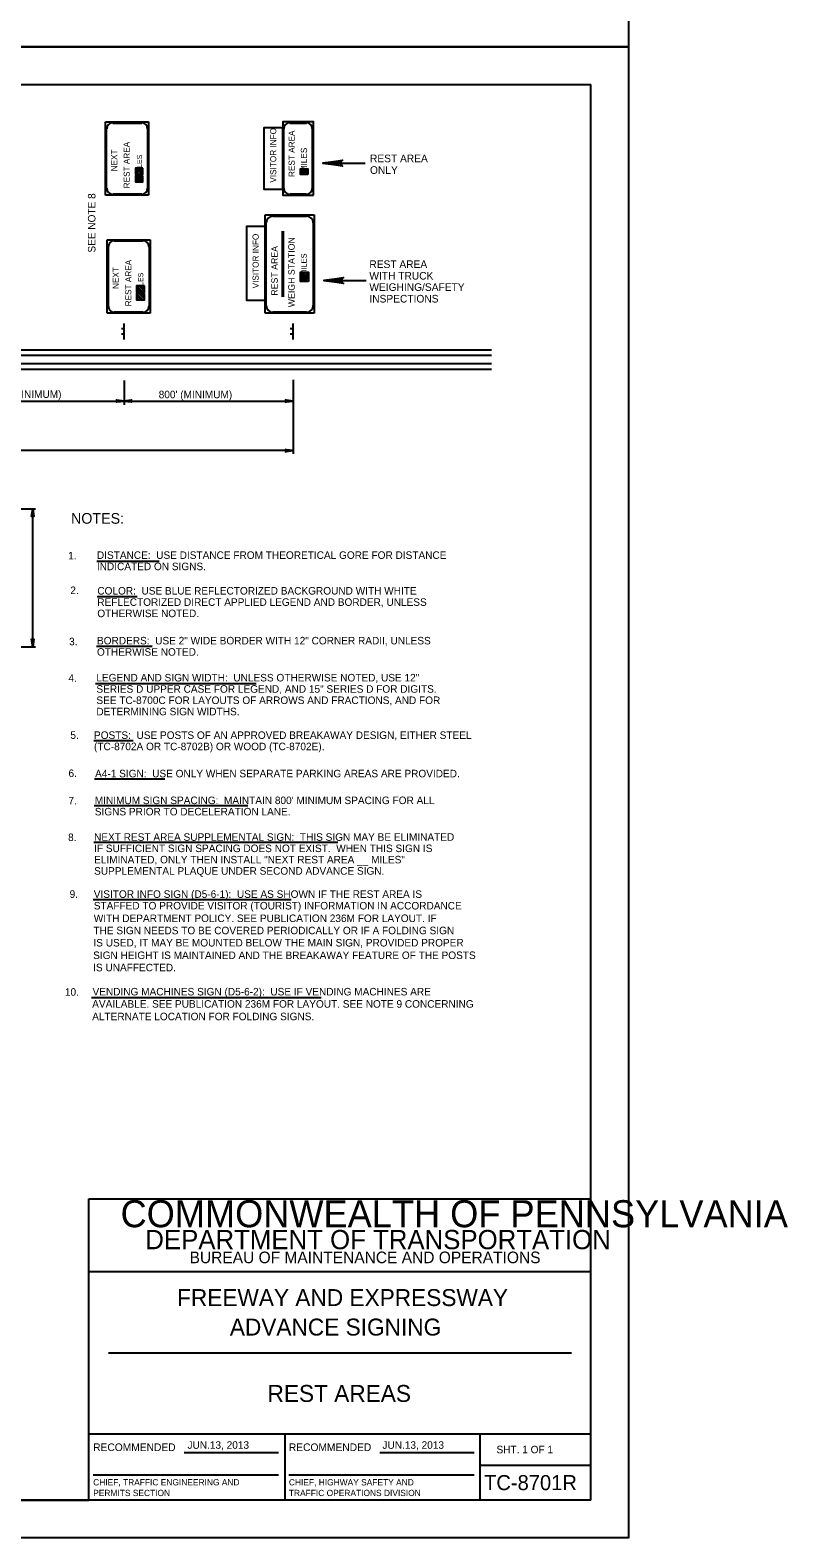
# Model space of a CAD drawing. Extents: x 649604 to 650509, y 298458 to 299646.
# Drawn here: x 650207 to 650509, y 298458 to 299058 of the extents above; entities that cross this region are included whole.
import ezdxf

# ---------------------------------------------------------------- set-up
doc = ezdxf.new("R2010")
doc.units = 0
for name, color, linetype in [('1', 7, 'Continuous'), ('2', 7, 'Continuous'), ('3', 7, 'Continuous'), ('PLT-BNDY', 7, 'Continuous')]:
    doc.layers.add(name, color=color, linetype=linetype)

# ---------------------------------------------------------------- blocks, each defined once
blk = doc.blocks.new('RARROW')
at = {"layer": '3'}
blk.add_lwpolyline([(-2.2695, 0.285), (-2.184875, 0.12075), (0, 0), (-2.2695, 0.285), (-2.38575, 0.384625), (0, 0), (-2.183125, -0.108), (-2.262875, -0.2705), (0, 0), (-2.38575, -0.379125), (-2.262875, -0.2705)], dxfattribs=at)

msp = doc.modelspace()

# ---------------------------------------------------------------- linework, layer by layer
at = {"layer": '1'}
for p, q in [((649644.31, 299036.63), (650430.31, 299036.63)), ((650430.31, 298472.63), (650430.31, 299036.63)), ((650230.31, 298472.63), (650230.31, 298592.63)), ((650230.31, 298592.63), (650430.31, 298592.63)), ((650430.31, 298563.63), (650230.31, 298563.63)), ((650238.06, 298531.31), (650422.56, 298531.31)), ((650230.31, 298499), (650430.31, 298499)), ((650308.31, 298499), (650308.31, 298472.63)), ((650386.19, 298472.63), (650386.19, 298499)), ((650268.24, 298491.57), (650305.87, 298491.57)), ((650346.24, 298491.57), (650383.87, 298491.57)), ((650386.19, 298486.63), (650430.31, 298486.63)), ((650231.99, 298482.68), (650305.87, 298482.68)), ((650309.99, 298482.68), (650383.87, 298482.68)), ((650430.31, 298472.63), (649644.31, 298472.63)), ((649644.31, 298472.63), (650230.31, 298472.63))]:
    msp.add_line(p, q, dxfattribs=at)
at = {"layer": '2'}
for p, q in [((650236.94, 298992.5), (650236.94, 299021.75)), ((650236.94, 299021.75), (650254.06, 299021.75)), ((650237.31, 298995.25), (650237.31, 299018.88)), ((650239.81, 299021.25), (650251.31, 299021.25)), ((650253.69, 299018.88), (650253.69, 298995.25)), ((650254.06, 299021.75), (650254.06, 298992.5)), ((650310.31, 299021.25), (650316.94, 299021.25)), ((650323.56, 299005.25), (650340.44, 299005.25)), ((650254.06, 298992.5), (650236.94, 298992.5)), ((650251.31, 298992.88), (650239.81, 298992.88)), ((650300.56, 298945.5), (650300.56, 298984.63)), ((650303.56, 298984.13), (650317.06, 298984.13)), ((650320.06, 298984.63), (650320.06, 298945.5)), ((650300.94, 298948.5), (650300.94, 298981.63)), ((650307.44, 298952), (650307.44, 298978.13)), ((650307.56, 298952), (650307.56, 298978.13)), ((650307.69, 298952), (650307.69, 298978.13)), ((650307.81, 298952), (650307.81, 298978.13)), ((650307.81, 298952), (650307.81, 298978.13)), ((650319.69, 298981.63), (650319.69, 298948.5)), ((650237.56, 298945.5), (650237.56, 298974.75)), ((650237.56, 298974.75), (650254.69, 298974.75)), ((650238.06, 298948.25), (650238.06, 298971.88)), ((650240.31, 298974.38), (650251.81, 298974.38)), ((650254.31, 298971.88), (650254.31, 298948.25)), ((650254.69, 298974.75), (650254.69, 298945.5)), ((650323.94, 298958.5), (650340.81, 298958.5)), ((650254.69, 298945.5), (650237.56, 298945.5)), ((650251.81, 298945.88), (650240.31, 298945.88)), ((650244.31, 298935), (650244.31, 298941.38)), ((650311.69, 298935), (650311.69, 298941.38)), ((650244.31, 298939.25), (650243.31, 298939.25)), ((650244.31, 298937.13), (650243.31, 298937.13)), ((650311.69, 298939.25), (650310.56, 298939.25)), ((650311.69, 298937.13), (650310.56, 298937.13)), ((649664.19, 298928.75), (650390.69, 298928.75)), ((649946.56, 298930.88), (650390.69, 298930.88)), ((650330.44, 298930.88), (650330.44, 298930.88)), ((649664.19, 298925.5), (650390.69, 298925.5)), ((649664.19, 298923.25), (650390.69, 298923.25)), ((650244.31, 298918.63), (650244.31, 298909)), ((650311.69, 298919), (650311.69, 298889.5)), ((650176.94, 298910.5), (650244.31, 298910.5)), ((650244.31, 298910.5), (650311.69, 298910.5)), ((650311.69, 298890.75), (649881.31, 298890.75)), ((650181.27, 298867.5), (650209, 298867.5)), ((650207.88, 298812.63), (650207.88, 298867.5)), ((650233.42, 298846.75), (650258.31, 298846.75)), ((650233.57, 298832.66), (650249.5, 298832.66)), ((650181.27, 298812.63), (650209, 298812.63)), ((650233.32, 298812.8), (650255.5, 298812.8)), ((650232.96, 298797.93), (650297, 298797.93)), ((650232.22, 298775.29), (650247.93, 298775.29)), ((650232.57, 298759.98), (650260.48, 298759.98)), ((650232.31, 298749.4), (650293.65, 298749.4)), ((650232.3, 298734.76), (650329.5, 298734.76)), ((650231.91, 298711.95), (650310.87, 298711.95)), ((650231.31, 298672.83), (650322.82, 298672.83))]:
    msp.add_line(p, q, dxfattribs=at)
for points in [[(650307.56, 298994.88), (650307.56, 299019.38), (650299.94, 299019.38), (650299.94, 298994.88)], [(650319.81, 298992.5), (650319.81, 299021.75), (650307.56, 299021.75), (650307.56, 298992.5)], [(650251.81, 299003.25), (650248.81, 299003.25), (650248.81, 299000.88), (650251.81, 299000.88)], [(650251.81, 299000.25), (650248.81, 299000.25), (650248.81, 298997.88), (650251.81, 298997.88)], [(650317.56, 299000.75), (650314.56, 299000.75), (650314.56, 299003), (650317.56, 299003)], [(650300.56, 298950.63), (650300.56, 298980), (650293.06, 298980), (650293.06, 298950.63)], [(650317.81, 298958.13), (650314.56, 298958.13), (650314.56, 298961.88), (650317.81, 298961.88)], [(650252.44, 298956.38), (650249.31, 298956.38), (650249.31, 298953.88), (650252.44, 298953.88)], [(650252.44, 298953.38), (650249.31, 298953.38), (650249.31, 298950.88), (650252.44, 298950.88)]]:
    msp.add_lwpolyline(points, close=True, dxfattribs=at)
for points in [[(650307.94, 298995.25), (650307.94, 299018.88)], [(650319.31, 299018.88), (650319.31, 298995.25)], [(650331.06, 299004.38), (650330.69, 299005), (650323.56, 299005.25), (650331.06, 299004.38), (650331.31, 299004.13), (650323.56, 299005.25), (650330.69, 299005.75), (650330.94, 299006.25), (650323.56, 299005.25), (650331.31, 299006.5), (650330.94, 299006.25)], [(650251.31, 299000.88), (650248.81, 299003.25)], [(650250.31, 299000.88), (650248.81, 299002.5)], [(650249.44, 299000.88), (650248.81, 299001.75)], [(650251.31, 298997.88), (650248.81, 299000.25)], [(650251.81, 298998.13), (650249.56, 299000.25)], [(650251.81, 299001.13), (650249.69, 299003.25)], [(650251.81, 299002), (650250.44, 299003.25)], [(650251.81, 298998.88), (650250.44, 299000.25)], [(650251.81, 299003), (650251.44, 299003.25)], [(650251.81, 298999.88), (650251.44, 299000.25)], [(650316.81, 299000.75), (650314.56, 299003)], [(650316.31, 299000.75), (650314.56, 299002.5)], [(650315.81, 299000.75), (650314.56, 299002)], [(650315.44, 299000.75), (650314.56, 299001.63)], [(650314.94, 299000.75), (650314.56, 299001.13)], [(650317.19, 299000.75), (650314.81, 299003)], [(650317.56, 299000.88), (650315.19, 299003)], [(650317.56, 299001.38), (650315.69, 299003)], [(650317.56, 299001.88), (650316.19, 299003)], [(650317.56, 299002.25), (650316.69, 299003)], [(650317.56, 299002.75), (650317.06, 299003)], [(650250.31, 298997.88), (650248.81, 298999.5)], [(650249.44, 298997.88), (650248.81, 298998.5)], [(650316.94, 298992.88), (650310.31, 298992.88)], [(650300.56, 298984.63), (650302.94, 298984.63), (650305.56, 298984.63), (650307.69, 298984.63), (650309.69, 298984.63), (650312.31, 298984.63), (650314.56, 298984.63), (650315.06, 298984.63), (650317.06, 298984.63), (650317.81, 298984.63), (650320.06, 298984.63)], [(650317.81, 298958.75), (650314.56, 298961.88)], [(650317.31, 298958.13), (650314.56, 298961.13)], [(650316.44, 298958.13), (650314.56, 298960.13)], [(650315.56, 298958.13), (650314.56, 298959.25)], [(650314.56, 298958.13), (650314.56, 298958.25)], [(650317.81, 298959.63), (650315.44, 298961.88)], [(650317.81, 298960.5), (650316.44, 298961.88)], [(650317.81, 298961.5), (650317.31, 298961.88)], [(650331.31, 298957.63), (650331.19, 298958.13), (650323.94, 298958.5), (650331.31, 298957.63), (650331.69, 298957.38), (650323.94, 298958.5), (650331.19, 298959), (650331.31, 298959.5), (650323.94, 298958.5), (650331.69, 298959.75), (650331.31, 298959.5)], [(650251.81, 298953.88), (650249.31, 298956.38)], [(650251.06, 298953.88), (650249.31, 298955.5)], [(650250.19, 298953.88), (650249.31, 298954.75)], [(650251.81, 298950.88), (650249.31, 298953.38)], [(650251.06, 298950.88), (650249.31, 298952.5)], [(650252.44, 298954.25), (650250.31, 298956.38)], [(650252.44, 298951.25), (650250.31, 298953.38)], [(650252.44, 298955.13), (650251.19, 298956.38)], [(650252.44, 298952), (650251.19, 298953.38)], [(650252.44, 298955.88), (650252.06, 298956.38)], [(650252.44, 298952.88), (650252.06, 298953.38)], [(650250.19, 298950.88), (650249.31, 298951.5)], [(650320.06, 298945.5), (650300.56, 298945.5)], [(650317.06, 298945.88), (650303.56, 298945.88)]]:
    msp.add_lwpolyline(points, dxfattribs=at)
for centre, radius, start, end in [((650239.81, 299018.91), 2.44, 90, 180), ((650251.22, 299018.91), 2.44, 0, 90), ((650310.4, 299018.91), 2.44, 90, 180), ((650316.92, 299018.91), 2.44, 0, 90), ((650239.81, 298995.29), 2.44, 180, 270), ((650251.22, 298995.29), 2.44, 270, 0), ((650310.4, 298995.29), 2.44, 180, 270), ((650316.92, 298995.29), 2.44, 270, 0), ((650303.6, 298981.54), 2.61, 90, 180), ((650317.08, 298981.54), 2.61, 0, 90), ((650240.41, 298971.93), 2.44, 90, 180), ((650251.82, 298971.93), 2.44, 0, 90), ((650240.41, 298948.3), 2.44, 180, 270), ((650251.82, 298948.3), 2.44, 270, 0), ((650303.6, 298948.5), 2.61, 180, 270), ((650317.08, 298948.5), 2.61, 270, 0)]:
    msp.add_arc(centre, radius, start, end, dxfattribs=at)
at = {"layer": 'PLT-BNDY'}
for points in [[(649604.31, 299645.63), (650445.31, 299645.63), (650445.31, 299051.63), (649604.31, 299051.63)], [(649604.31, 299051.63), (650445.31, 299051.63), (650445.31, 298457.63), (649604.31, 298457.63)]]:
    msp.add_lwpolyline(points, close=True, dxfattribs=at)

# ---------------------------------------------------------------- block references
at = {"layer": '2', "xscale": 1.2574347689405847, "yscale": 1.3092961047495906}
for p in [(650244.31, 298910.5), (650311.69, 298910.5), (650311.69, 298890.75)]:
    msp.add_blockref('RARROW', p, dxfattribs=at)
for p, rotation in [((650244.31, 298910.5), 180), ((650207.88, 298867.5), 89.99999999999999), ((650207.88, 298812.63), -90.00000000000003)]:
    msp.add_blockref('RARROW', p, dxfattribs=dict(at, rotation=rotation))

# ---------------------------------------------------------------- texts
at = {"layer": '1'}
for s, height, p in [('COMMONWEALTH OF PENNSYLVANIA', 10.7828, (650242.9, 298581.36)), ('DEPARTMENT OF TRANSPORTATION', 7.6837, (650252.76, 298572.61)), ('BUREAU OF MAINTENANCE AND OPERATIONS', 4.6253, (650270.41, 298567.04)), ('FREEWAY AND EXPRESSWAY', 6.75, (650265.42, 298549.97)), ('ADVANCE SIGNING', 6.75, (650286.45, 298538.22)), ('REST AREAS', 6.75, (650301.47, 298511.78)), ('RECOMMENDED', 3.048, (650231.99, 298492.2)), ('RECOMMENDED', 3.048, (650309.99, 298492.2)), ('SHT. 1 OF 1', 3, (650392.74, 298491.31)), ('CHIEF, TRAFFIC ENGINEERING AND', 2.5, (650231.99, 298478.51)), ('CHIEF, HIGHWAY SAFETY AND', 2.5, (650309.99, 298478.51)), ('TC-8701R', 6, (650387.77, 298476.63)), ('PERMITS SECTION', 2.5, (650231.99, 298474.26)), ('TRAFFIC OPERATIONS DIVISION', 2.5, (650309.99, 298474.26))]:
    msp.add_text(s, height=height, dxfattribs=at).set_placement(p)
at = {"layer": '2'}
for s, height, p in [('VISITOR INFO', 2.4443, (650304.94, 298997.5)), ('REST AREA', 2.444, (650312.31, 298999.75)), ('REST AREA', 2.443, (650246.56, 298995.25)), ('NEXT', 2.443, (650241.56, 299002)), ('   MILES', 2.035, (650251.44, 298997.88)), ('    MILES', 2.443, (650317.19, 298998)), ('SEE NOTE 8', 3, (650232.89, 298969.63)), ('VISITOR INFO', 2.4443, (650297.94, 298955.38)), ('REST AREA', 2.608, (650305.56, 298952.5)), ('WEIGH STATION', 2.6078, (650312.31, 298947.88)), ('REST AREA', 2.443, (650247.19, 298948.25)), ('  MILES', 2.174, (650317.06, 298958.63)), ('NEXT', 2.443, (650242.19, 298955.13)), ('   MILES', 2.035, (650251.94, 298950.88))]:
    msp.add_text(s, height=height, rotation=90, dxfattribs=at).set_placement(p)
for s, height, p in [('REST AREA', 3.041, (650342.31, 299005.63)), ('ONLY', 3.041, (650342.31, 299001)), ('REST AREA', 3.041, (650342.06, 298963.5)), ('WITH TRUCK', 3.041, (650342.06, 298958.88)), ('WEIGHING/SAFETY', 3.0405, (650342.06, 298954.38)), ('INSPECTIONS', 3.0405, (650342.06, 298949.75)), ("800' (MINIMUM)", 3, (650190.06, 298911.75)), ("800' (MINIMUM)", 3, (650258.1, 298911.61)), ('NOTES:', 4.25, (650223.15, 298861.63)), ('1.  ', 3, (650222, 298847.41)), ('DISTANCE:  USE DISTANCE FROM THEORETICAL GORE FOR DISTANCE', 3, (650233.47, 298847.62)), ('INDICATED ON SIGNS.', 3, (650233.47, 298843.12)), ('2.  ', 3, (650222.89, 298833.61)), ('COLOR:  USE BLUE REFLECTORIZED BACKGROUND WITH WHITE', 3, (650233.63, 298833.41)), ('REFLECTORIZED DIRECT APPLIED LEGEND AND BORDER, UNLESS', 3, (650233.63, 298828.91)), ('OTHERWISE NOTED.', 3, (650233.63, 298824.41)), ('3.  ', 3, (650222.38, 298813.21)), ('BORDERS:  USE 2" WIDE BORDER WITH 12" CORNER RADII, UNLESS ', 3, (650233.5, 298813.55)), ('OTHERWISE NOTED.', 3, (650233.5, 298809.05)), ('LEGEND AND SIGN WIDTH:  UNLESS OTHERWISE NOTED, USE 12"', 3, (650233.25, 298798.8)), ('4.', 3, (650222.13, 298798.69)), ('SERIES D UPPER CASE FOR LEGEND, AND 15" SERIES D FOR DIGITS.', 3, (650233.25, 298794.3)), ('SEE TC-8700C FOR LAYOUTS OF ARROWS AND FRACTIONS, AND FOR ', 3, (650233.25, 298789.8)), ('DETERMINING SIGN WIDTHS.', 3, (650233.25, 298785.3)), ('5.  ', 3, (650222.89, 298775.93)), ('POSTS:  USE POSTS OF AN APPROVED BREAKAWAY DESIGN, EITHER STEEL', 3, (650232.31, 298775.9)), ('(TC-8702A OR TC-8702B) OR WOOD (TC-8702E).', 3, (650232.31, 298771.4)), ('6.  ', 3, (650222.14, 298760.74)), ('A4-1 SIGN:  USE ONLY WHEN SEPARATE PARKING AREAS ARE PROVIDED.', 3, (650232.75, 298760.6)), ('7.  ', 3, (650222.12, 298749.81)), ('SIGNS PRIOR TO DECELERATION LANE.', 3, (650232.63, 298745.43)), ("MINIMUM SIGN SPACING:  MAINTAIN 800' MINIMUM SPACING FOR ALL", 3, (650232.63, 298749.93)), ('8.  ', 3, (650221.97, 298735.21)), ('NEXT REST AREA SUPPLEMENTAL SIGN:  THIS SIGN MAY BE ELIMINATED', 3, (650232.34, 298735.31)), ('IF SUFFICIENT SIGN SPACING DOES NOT EXIST.  WHEN THIS SIGN IS', 3, (650232.34, 298730.81)), ('SUPPLEMENTAL PLAQUE UNDER SECOND ADVANCE SIGN.', 3, (650232.34, 298721.81)), ('ELIMINATED, ONLY THEN INSTALL "NEXT REST AREA __ MILES" ', 3, (650232.34, 298726.31)), ('9.  ', 3, (650222.6, 298712.59)), ('VISITOR INFO SIGN (D5-6-1):  USE AS SHOWN IF THE REST AREA IS', 3, (650232.22, 298712.58)), ('WITH DEPARTMENT POLICY. SEE PUBLICATION 236M FOR LAYOUT. IF', 3, (650232.22, 298702.95)), ('STAFFED TO PROVIDE VISITOR (TOURIST) INFORMATION IN ACCORDANCE', 3, (650232.22, 298707.96)), ('THE SIGN NEEDS TO BE COVERED PERIODICALLY OR IF A FOLDING SIGN', 3, (650232.09, 298698.08)), ('IS USED, IT MAY BE MOUNTED BELOW THE MAIN SIGN, PROVIDED PROPER', 3, (650232.09, 298693.21)), ('SIGN HEIGHT IS MAINTAINED AND THE BREAKAWAY FEATURE OF THE POSTS', 3, (650231.97, 298688.21)), ('IS UNAFFECTED.', 3, (650231.97, 298683.33)), ('10.   ', 3, (650220.71, 298673.59)), ('VENDING MACHINES SIGN (D5-6-2):  USE IF VENDING MACHINES ARE', 3, (650231.72, 298673.71)), ('AVAILABLE. SEE PUBLICATION 236M FOR LAYOUT. SEE NOTE 9 CONCERNING', 3, (650231.59, 298668.83)), ('ALTERNATE LOCATION FOR FOLDING SIGNS.', 3, (650231.59, 298663.83)), ('JUN.13, 2013', 3, (650269.57, 298493.11)), ('JUN.13, 2013', 3, (650347.27, 298493.11))]:
    msp.add_text(s, height=height, dxfattribs=at).set_placement(p)

doc.saveas('drawing.dxf')
